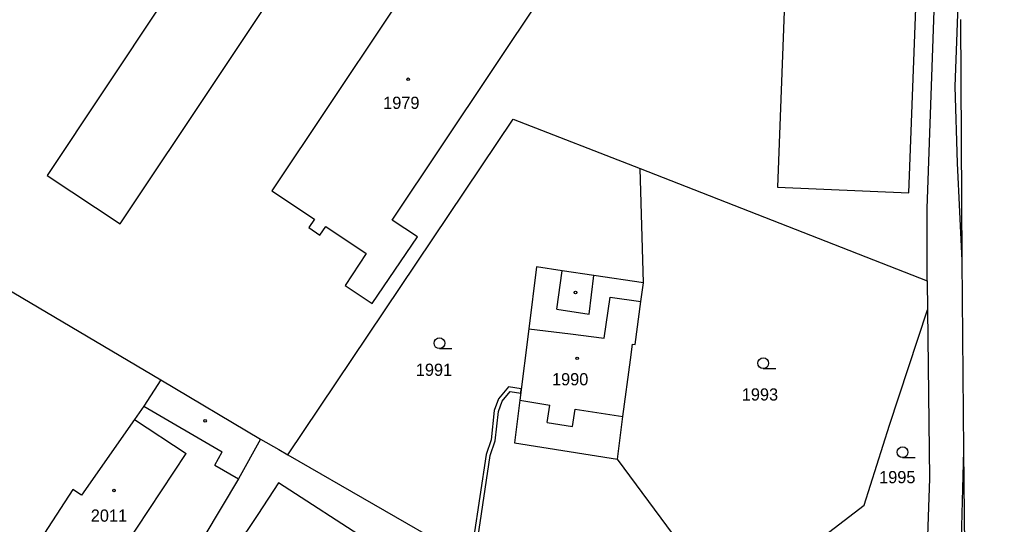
# Model space of a CAD drawing. Extents: x -562167 to -556918, y -1077891 to -1070763.
# Drawn here: x -560292.3 to -560153.7, y -1077191.8 to -1077121.5 of the extents above; entities that cross this region are included whole.
import ezdxf

# ---------------------------------------------------------------- set-up
doc = ezdxf.new("R2010")
doc.units = 0
for name, color, linetype in [('Hranice parcel', 7, 'Continuous'), ('Parcelní čísla', 7, 'Continuous'), ('Vnitřní kresba', 7, 'Continuous'), ('Věcná břemena k části', 7, 'Continuous'), ('Značky budov', 7, 'Continuous'), ('Značky kultur', 7, 'Continuous')]:
    doc.layers.add(name, color=color, linetype=linetype)

msp = doc.modelspace()

# ---------------------------------------------------------------- linework, layer by layer
at = {"layer": 'Hranice parcel'}
for p, q in [((-560160.99, -1077155.03), (-560161.15, -1077121.46)), ((-560205.4, -1077158.14), (-560205.85, -1077142.25)), ((-560205.85, -1077142.25), (-560165.84, -1077157.89)), ((-560160.73, -1077181.51), (-560160.99, -1077155.03)), ((-560295.89, -1077157.95), (-560272.68, -1077171.66)), ((-560165.84, -1077157.89), (-560165.79, -1077161.9)), ((-560272.68, -1077171.66), (-560258.79, -1077179.92)), ((-560201.23, -1077193.27), (-560209.03, -1077182.73)), ((-560160.55, -1077199.12), (-560160.73, -1077181.51))]:
    msp.add_line(p, q, dxfattribs=at)
for points in [[(-560160.99, -1077155.03), (-560161.61, -1077141.5), (-560161.97, -1077130.79), (-560160.9, -1077101.8), (-560158.8, -1077080.3), (-560153.74, -1077030.09), (-560153.76, -1077022.75)], [(-560165.84, -1077157.89), (-560165.84, -1077147.82), (-560163.5, -1077080.8), (-560161.95, -1077050.53)], [(-560165.98, -1077081.83), (-560184.3, -1077081.05), (-560186.7, -1077144.83), (-560168.43, -1077145.6), (-560165.98, -1077081.83)], [(-560238.22, -1077089.84), (-560248.49, -1077083.07), (-560288.52, -1077143.22), (-560278.34, -1077149.95), (-560238.22, -1077089.84)], [(-560228.64, -1077111.96), (-560233, -1077109.08), (-560257.19, -1077145.32), (-560251.24, -1077149.27), (-560252.04, -1077150.47), (-560250.48, -1077151.5), (-560249.68, -1077150.31), (-560244.02, -1077154.07), (-560246.98, -1077158.54), (-560243.2, -1077161.05), (-560236.88, -1077151.77), (-560240.4, -1077149.42), (-560219.46, -1077118.02), (-560224.47, -1077114.71)], [(-560254.94, -1077182.14), (-560223.55, -1077135.33), (-560205.85, -1077142.25)], [(-560205.4, -1077158.14), (-560212.31, -1077157.12), (-560216.71, -1077156.47), (-560220.29, -1077155.94), (-560221.37, -1077164.56), (-560222.62, -1077174.51), (-560223.36, -1077180.47), (-560209.03, -1077182.73)], [(-560209.03, -1077182.73), (-560208.25, -1077176.79), (-560207.21, -1077168.89), (-560206.92, -1077166.71), (-560206.54, -1077166.76), (-560205.75, -1077160.74), (-560205.4, -1077158.14)], [(-560180.22, -1077193.39), (-560174.64, -1077189.12), (-560171.12, -1077177.98), (-560165.79, -1077161.9)], [(-560165.79, -1077161.9), (-560165.52, -1077185.43), (-560165.89, -1077196.1)], [(-560272.68, -1077171.66), (-560275.02, -1077175.32), (-560276.31, -1077177.2), (-560283.72, -1077187.76), (-560284.93, -1077186.97), (-560290.1, -1077194.91), (-560281.47, -1077200.53), (-560278.83, -1077196.56), (-560271.63, -1077201.85)], [(-560258.79, -1077179.92), (-560261.85, -1077185.46), (-560271.63, -1077201.85)], [(-560258.79, -1077179.92), (-560256.22, -1077181.4), (-560254.94, -1077182.14)], [(-560254.94, -1077182.14), (-560231.06, -1077195.89), (-560228.18, -1077195.69)], [(-560162.83, -1077209.41), (-560161.09, -1077193.89), (-560160.73, -1077181.51)], [(-560242.23, -1077201.31), (-560239.4, -1077196.92), (-560242.68, -1077194.81), (-560242.25, -1077194.13), (-560243.04, -1077193.62), (-560243.48, -1077194.29), (-560256.28, -1077186.04), (-560259.16, -1077190.42), (-560262.23, -1077195.1), (-560262.92, -1077194.65), (-560263.66, -1077195.72), (-560262.95, -1077196.19), (-560265.61, -1077200.23), (-560248.61, -1077211.2), (-560247.95, -1077210.17), (-560238.78, -1077216.08), (-560233.82, -1077208.4), (-560242.99, -1077202.49), (-560242.23, -1077201.31)]]:
    msp.add_lwpolyline(points, dxfattribs=at)
at = {"layer": 'Vnitřní kresba'}
for p, q in [((-560217.47, -1077161.82), (-560216.71, -1077156.47)), ((-560212.97, -1077162.51), (-560212.31, -1077157.12)), ((-560210.88, -1077165.86), (-560210.05, -1077160.17)), ((-560210.05, -1077160.17), (-560205.75, -1077160.74)), ((-560217.47, -1077161.82), (-560212.97, -1077162.51)), ((-560221.37, -1077164.56), (-560215.57, -1077165.28)), ((-560215.57, -1077165.28), (-560210.88, -1077165.86)), ((-560275.02, -1077175.32), (-560264.12, -1077181.71)), ((-560222.62, -1077174.51), (-560218.43, -1077175.18)), ((-560218.82, -1077177.63), (-560218.43, -1077175.18)), ((-560215.29, -1077178.19), (-560214.9, -1077175.74)), ((-560214.9, -1077175.74), (-560208.25, -1077176.79)), ((-560276.31, -1077177.2), (-560269.11, -1077181.94)), ((-560218.82, -1077177.63), (-560215.29, -1077178.19)), ((-560278.83, -1077196.56), (-560269.11, -1077181.94)), ((-560265.15, -1077183.55), (-560264.12, -1077181.71)), ((-560265.15, -1077183.55), (-560261.85, -1077185.46))]:
    msp.add_line(p, q, dxfattribs=at)
at = {"layer": 'Věcná břemena k části'}
msp.add_lwpolyline([(-560227.32, -1077182.09), (-560229.1, -1077193.77), (-560228.88, -1077195.74), (-560228.18, -1077195.69), (-560228.5, -1077193.79), (-560226.74, -1077182.23), (-560226.05, -1077180.19), (-560225.6, -1077176.08), (-560225.1, -1077174.64), (-560223.96, -1077173.3), (-560222.5, -1077173.53), (-560222.42, -1077172.94), (-560224.2, -1077172.66), (-560225.62, -1077174.34), (-560226.18, -1077175.94), (-560226.63, -1077180.05)], close=True, dxfattribs=at)
at = {"layer": 'Značky budov'}
for centre in [(-560238.19, -1077129.79), (-560214.87, -1077159.5), (-560214.63, -1077168.68), (-560266.49, -1077177.38), (-560279.19, -1077187.09)]:
    msp.add_circle(centre, 0.175, dxfattribs=at)
at = {"layer": 'Značky kultur'}
for p, q in [((-560233.83, -1077167.32), (-560232.08, -1077167.32)), ((-560188.7, -1077170.11), (-560186.95, -1077170.11)), ((-560169.28, -1077182.51), (-560167.53, -1077182.51))]:
    msp.add_line(p, q, dxfattribs=at)
for centre in [(-560233.83, -1077166.57), (-560188.7, -1077169.36), (-560169.28, -1077181.76)]:
    msp.add_circle(centre, 0.75, dxfattribs=at)

# ---------------------------------------------------------------- texts
at = {"layer": 'Parcelní čísla'}
for s, p in [('1979', (-560241.67, -1077133.92)), ('1991', (-560237.12, -1077171.12)), ('1990', (-560218.14, -1077172.44)), ('1993', (-560191.69, -1077174.56)), ('1995', (-560172.55, -1077186.08)), ('2011', (-560282.42, -1077191.44))]:
    msp.add_text(s, height=1.7, dxfattribs=at).set_placement(p)

doc.saveas('drawing.dxf')
